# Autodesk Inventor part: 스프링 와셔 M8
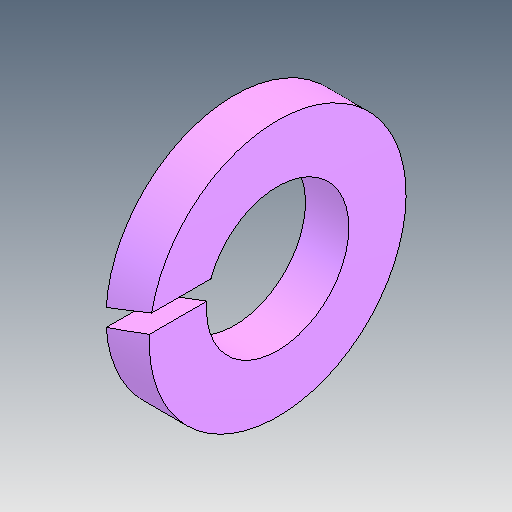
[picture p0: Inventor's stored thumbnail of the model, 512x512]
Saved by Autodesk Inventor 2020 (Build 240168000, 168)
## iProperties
Created: 2024-11
Part Number: 스프링 와셔 M8
Material: 강철, 연강
Description: 스프링 잠금 와셔
Document SubType Name: Modeling
Designer: shin
Density: 7.85 g/cm^3
Appearance: 기본값
Author: jhkim
Sending System: Autodesk Inventor 2025
Preprocessor: ST-DEVELOPER v20
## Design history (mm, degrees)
feature "Solid1"
node "솔리드1"
